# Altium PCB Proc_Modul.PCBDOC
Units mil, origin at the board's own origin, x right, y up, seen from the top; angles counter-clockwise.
Board outline 5390 x 3140 mil, 2 copper layers (Top Layer, Bottom Layer); 23 components, 59 nets, 260 pads, 83 vias.
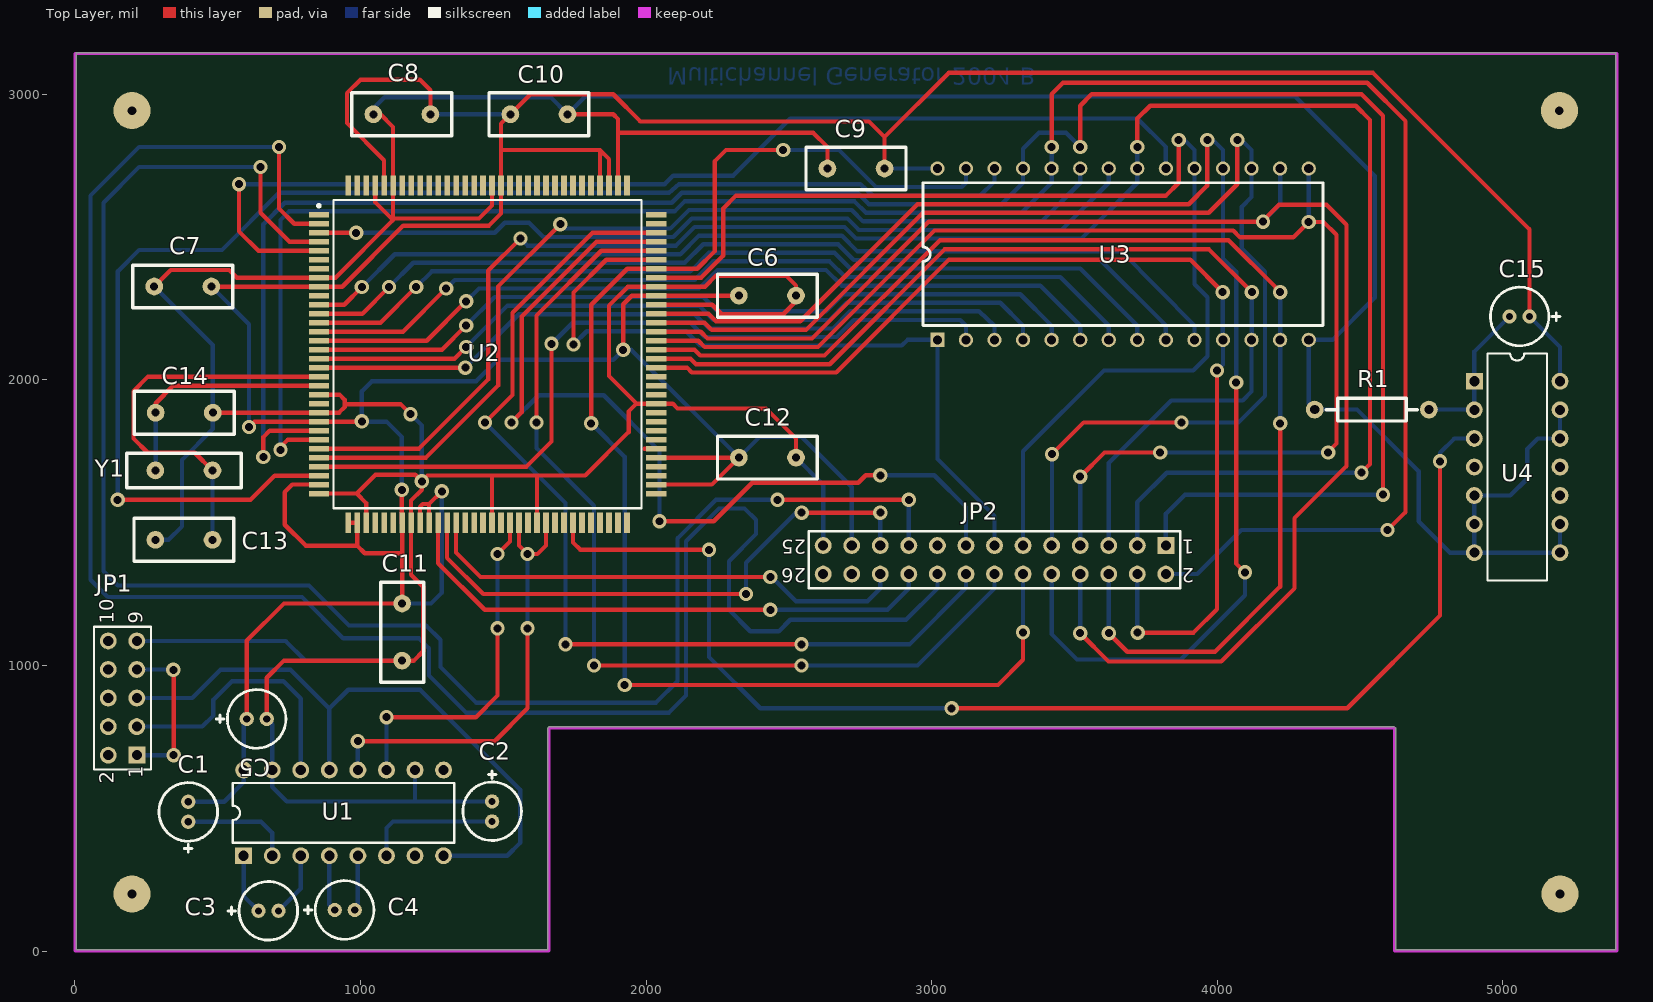
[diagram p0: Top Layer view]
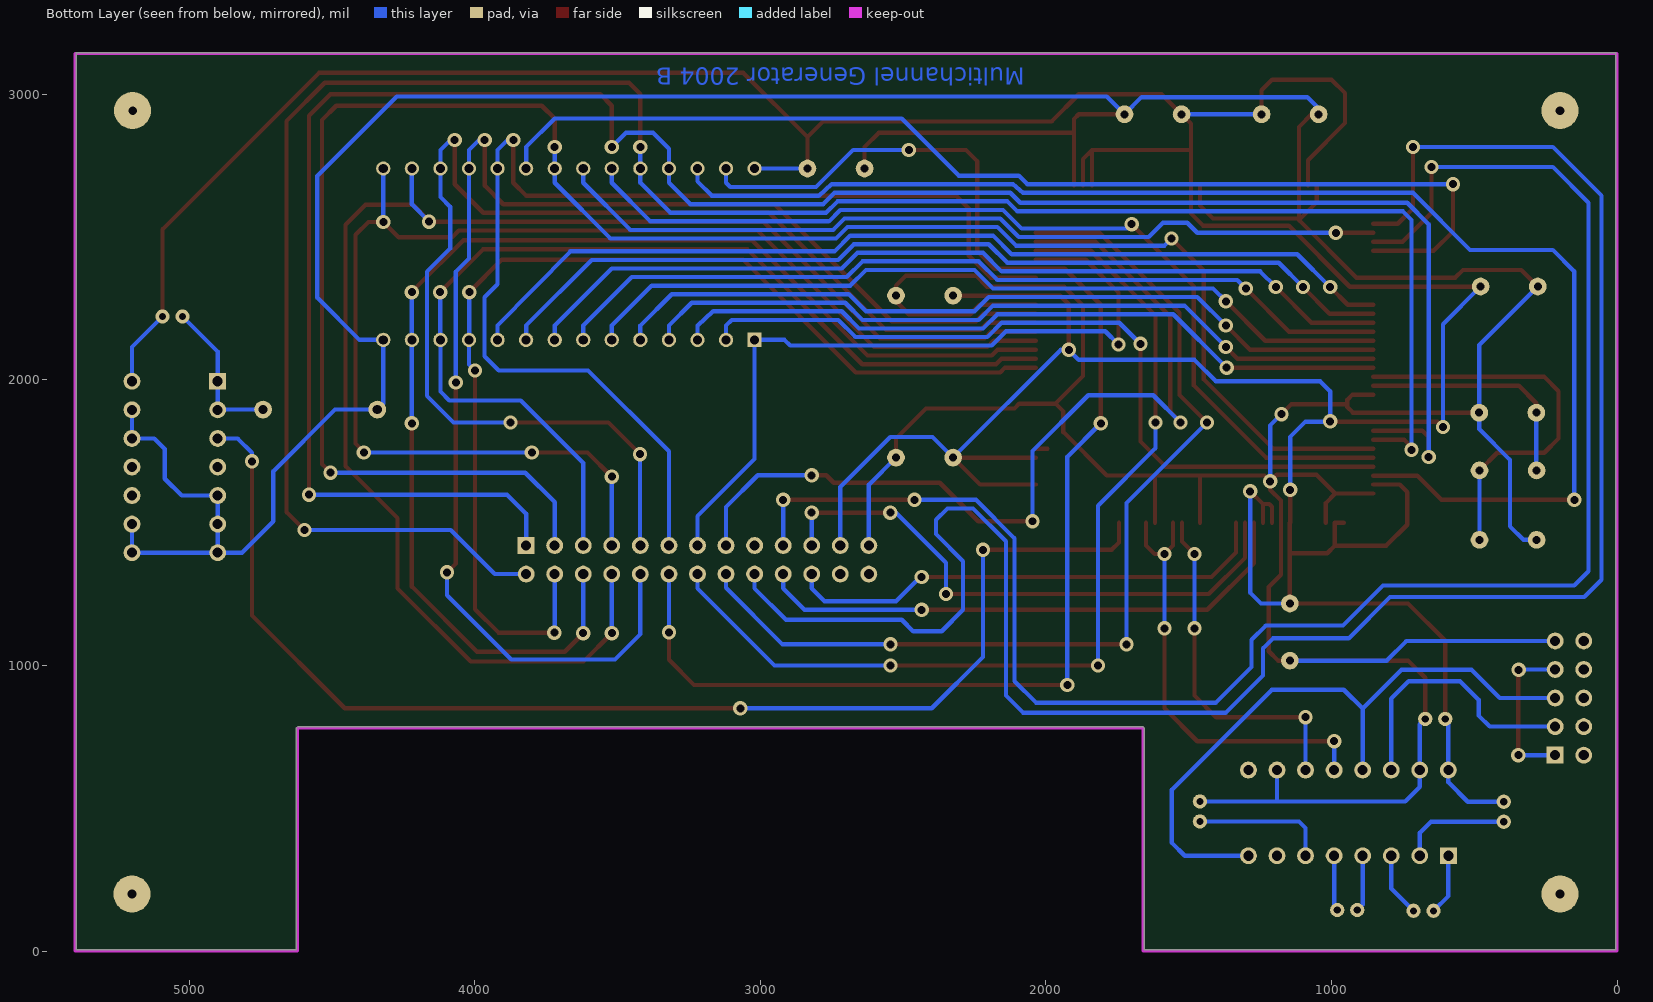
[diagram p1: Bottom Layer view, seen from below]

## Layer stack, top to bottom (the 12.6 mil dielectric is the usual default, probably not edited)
Top Layer: signal copper 1.4
Dielectric: dielectric 12.6, FR-4, Dk 4.8
Bottom Layer: signal copper 1.4

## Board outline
5,5 1655,5 1655,780 1660,785 4620,785 4625,780 4625,5 5395,5 5395,3145 5,3145

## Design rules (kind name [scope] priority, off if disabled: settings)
Clearance [All] p1: gap=10
ComponentClearance [All] p1: gap=10 collisioncheckmode=0
PolygonConnect [All] p1: connectstyle=Relief reliefconductorwidth=10 reliefentries=4 polygonreliefangle="90 Angle"
RoutingLayers [All] p1: top layer=Vertical bottom layer=Horizontal
RoutingVias [All] p1: holewidth=28 width=50 viastyle="Through Hole" minholewidth=28 minwidth=50 maxholewidth=28 maxwidth=50
SolderMaskExpansion [All] p1: expansion=4
TestPointUsage [All] p1: valid=0 allowmultiple=FALSE
Testpoint [All] p1: side=15 testpointundercomponent=TRUE minsize=40 maxsize=100 preferedsize=60 minholesize=0 maxholesize=40 preferedholesize=32 testpointgrid=1 style=1023 order=1234567890
Width 15mil [All] p1: maxlimit=20 minlimit=10 preferedwidth=10 toplayer_minwidth=15 toplayer_prefwidth=15 bottomlayer_minwidth=15 bottomlayer_prefwidth=15 minimp=50.000000 maximp=50.000000 favimp=50.000000
16 further rules are at their usual default settings.

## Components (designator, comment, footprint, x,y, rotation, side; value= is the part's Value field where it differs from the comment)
C1 "1uF" RB.07/.2 397,453 r90 top
C2 "1uF" RB.07/.2 1461,524 r270 top
C3 "1uF" RB.07/.2 643,141 r0 top
C4 "1uF" RB.07/.2 910,144 r0 top
C5 "4u7" RB.07/.2 602,813 r0 top
C6 "" RAD-0.2 2525,2295 r180 top
C7 "" RAD-0.2 278,2327 r0 top
C8 "" RAD-0.2 1045,2930 r0 top
C9 "" RAD-0.2 2635,2740 r0 top
C10 "100nF" RAD-0.2 1725,2930 r180 top
C11 "100nF" RAD-0.2 1146,1017 r90 top
C12 "100nF" RAD-0.2 2525,1728 r180 top
C13 "" RAD-0.2 482,1440 r180 top
C14 "" RAD-0.2 283,1885 r0 top
C15 "Cap Pol1" RB.07/.2 5093,2222 r180 top
JP1 "Header 5X2" HDR2X5 217,686 r90 top
JP2 "Header 13X2" HDR2X13 3820,1420 r180 top
R1 "Res2" AXIAL-0.4 4341,1896 r0 top
U1 "MAX232ACPE" DIP-16/X1.5 941,484 r0 top
U2 "ADSP-2181KS-160" QFP28x28-G128/Y1.8N 1445,2090 r0 top
U3 "27512" DIP28 3020,2140 r90 top
U4 "4093" DIP-14 5050,1695 r270 top
Y1 "XTAL" XTAL1 282,1683 r0 top

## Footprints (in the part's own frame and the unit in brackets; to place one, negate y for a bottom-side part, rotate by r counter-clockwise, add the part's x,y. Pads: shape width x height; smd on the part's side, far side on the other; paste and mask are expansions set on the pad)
AXIAL-0.4 [mil]
  round 62 hole 32: 1(0,0) 2(400,0)
  silkscreen extent 40,-40 360,40
DIP28 [mil]
  rect 50x50 hole 32: 1(0,0)
  round 50 hole 32: 2(0,-100) 3(0,-200) 4(0,-300) 5(0,-400) 6(0,-500) 7(0,-600) 8(0,-700) 9(0,-800) 10(0,-900) 11(0,-1000) 12(0,-1100) 13(0,-1200) 14(0,-1300) 15(600,-1300) 16(600,-1200) 17(600,-1100) 18(600,-1000) 19(600,-900) 20(600,-800) 21(600,-700) 22(600,-600) 23(600,-500) 24(600,-400) 25(600,-300) 26(600,-200) 27(600,-100) 28(600,0)
  silkscreen extent 50,-1350 550,50
DIP-14 [mm]
  rect 1.5x1.5 hole 0.9: 1(-7.62,-3.81)
  round 1.5 hole 0.9: 2(-5.08,-3.81) 3(-2.54,-3.81) 4(0,-3.81) 5(2.54,-3.81) 6(5.08,-3.81) 7(7.62,-3.81) 8(7.62,3.81) 9(5.08,3.81) 10(2.54,3.81) 11(0,3.81) 12(-2.54,3.81) 13(-5.08,3.81) 14(-7.62,3.81)
  silkscreen extent -10.1,-2.65 10.1,2.65
DIP-16/X1.5 [mm]
  rect 1.5x1.5 hole 0.9: 1(-8.89,-3.81)
  round 1.5 hole 0.9: 2(-6.35,-3.81) 3(-3.81,-3.81) 4(-1.27,-3.81) 5(1.27,-3.81) 6(3.81,-3.81) 7(6.35,-3.81) 8(8.89,-3.81) 9(8.89,3.81) 10(6.35,3.81) 11(3.81,3.81) 12(1.27,3.81) 13(-1.27,3.81) 14(-3.81,3.81) 15(-6.35,3.81) 16(-8.89,3.81)
  silkscreen extent -9.85,-2.65 9.85,2.65
HDR2X5 [mm]
  rect 1.5x1.5 hole 0.9: 1(0,0)
  round 1.5 hole 0.9: 2(0,2.54) 3(2.54,0) 4(2.54,2.54) 5(5.08,0) 6(5.08,2.54) 7(7.62,0) 8(7.62,2.54) 9(10.16,0) 10(10.16,2.54)
  silkscreen extent -1.27,-1.27 11.43,3.81
HDR2X13 [mm]
  rect 1.5x1.5 hole 0.9: 1(0,0)
  round 1.5 hole 0.9: 2(0,2.54) 3(2.54,0) 4(2.54,2.54) 5(5.08,0) 6(5.08,2.54) 7(7.62,0) 8(7.62,2.54) 9(10.16,0) 10(10.16,2.54) 11(12.7,0) 12(12.7,2.54) 13(15.24,0) 14(15.24,2.54) 15(17.78,0) 16(17.78,2.54) 17(20.32,0) 18(20.32,2.54) 19(22.86,0) 20(22.86,2.54) 21(25.4,0) 22(25.4,2.54) 23(27.94,0) 24(27.94,2.54) 25(30.48,0) 26(30.48,2.54)
  silkscreen extent -1.27,-1.27 31.75,3.81
QFP28x28-G128/Y1.8N [mm]
  rect 1.8x0.5 smd: 1(-15,12.4) 2(-15,11.6) 3(-15,10.8) 4(-15,10) 5(-15,9.2) 6(-15,8.4) 7(-15,7.6) 8(-15,6.8) 9(-15,6) 10(-15,5.2) 11(-15,4.4) 12(-15,3.6) 13(-15,2.8) 14(-15,2) 15(-15,1.2) 16(-15,0.4) 17(-15,-0.4) 18(-15,-1.2) 19(-15,-2) 20(-15,-2.8) 21(-15,-3.6) 22(-15,-4.4) 23(-15,-5.2) 24(-15,-6) 25(-15,-6.8) 26(-15,-7.6) 27(-15,-8.4) 28(-15,-9.2) 29(-15,-10) 30(-15,-10.8) 31(-15,-11.6) 32(-15,-12.4) 65(15,-12.4) 66(15,-11.6) 67(15,-10.8) 68(15,-10) 69(15,-9.2) 70(15,-8.4) 71(15,-7.6) 72(15,-6.8) 73(15,-6) 74(15,-5.2) 75(15,-4.4) 76(15,-3.6) 77(15,-2.8) 78(15,-2) 79(15,-1.2) 80(15,-0.4) 81(15,0.4) 82(15,1.2) 83(15,2) 84(15,2.8) 85(15,3.6) 86(15,4.4) 87(15,5.2) 88(15,6) 89(15,6.8) 90(15,7.6) 91(15,8.4) 92(15,9.2) 93(15,10) 94(15,10.8) 95(15,11.6) 96(15,12.4)
  rect 0.5x1.8 smd: 33(-12.4,-15) 34(-11.6,-15) 35(-10.8,-15) 36(-10,-15) 37(-9.2,-15) 38(-8.4,-15) 39(-7.6,-15) 40(-6.8,-15) 41(-6,-15) 42(-5.2,-15) 43(-4.4,-15) 44(-3.6,-15) 45(-2.8,-15) 46(-2,-15) 47(-1.2,-15) 48(-0.4,-15) 49(0.4,-15) 50(1.2,-15) 51(2,-15) 52(2.8,-15) 53(3.6,-15) 54(4.4,-15) 55(5.2,-15) 56(6,-15) 57(6.8,-15) 58(7.6,-15) 59(8.4,-15) 60(9.2,-15) 61(10,-15) 62(10.8,-15) 63(11.6,-15) 64(12.4,-15) 97(12.4,15) 98(11.6,15) 99(10.8,15) 100(10,15) 101(9.2,15) 102(8.4,15) 103(7.6,15) 104(6.8,15) 105(6,15) 106(5.2,15) 107(4.4,15) 108(3.6,15) 109(2.8,15) 110(2,15) 111(1.2,15) 112(0.4,15) 113(-0.4,15) 114(-1.2,15) 115(-2,15) 116(-2.8,15) 117(-3.6,15) 118(-4.4,15) 119(-5.2,15) 120(-6,15) 121(-6.8,15) 122(-7.6,15) 123(-8.4,15) 124(-9.2,15) 125(-10,15) 126(-10.8,15) 127(-11.6,15) 128(-12.4,15)
  silkscreen extent -15.12,-13.7 13.7,13.7
RAD-0.2 [mil]
  round 62 hole 28: 1(0,0) 2(200,0)
  silkscreen extent -75,-75 275,75
RB.07/.2 [mil]
  round 50 hole 25: 1(0,0) 2(70,0)
  silkscreen extent -107,-103 137,102
XTAL1 [mil]
  round 62 hole 28: 1(0,0) 2(200,0)
  silkscreen extent -100,-60 300,60

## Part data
C1 C2 C3 C4 C5: library part ELECTRO1
C6 C7 C8 C9 C10 C11 C12 C13 C14: library part Cap, "Capacitor"
C15: "Polarized Capacitor (Radial)"
JP1: "Header, 5-Pin, Dual row"
JP2: "Header, 13-Pin, Dual row"
R1: "Resistor"
U1: "+5V Powered, Multi-Channel RS-232 Driver/Receiver"
U2: "40 MIPS, 5V, 2 Serial Ports, Host Port, 80 KB RAM"
Y1: "Crystal Oscillator"

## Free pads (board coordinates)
  round 130 hole 30: 0(200,200) 0(200,2943) 0(5198,2943) 0(5200,200)

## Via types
v1: diameter 50, hole 28, Top Layer to Bottom Layer, 83 vias

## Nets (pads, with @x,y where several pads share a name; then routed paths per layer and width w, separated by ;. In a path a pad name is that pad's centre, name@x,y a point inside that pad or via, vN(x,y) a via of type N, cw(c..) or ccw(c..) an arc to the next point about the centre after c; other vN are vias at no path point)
/BMS: U2.5 U3.20 | length 3929.2
  Top Layer w15: v1(575,2685) 575,2520 642.8,2452.2 U2.5
  Bottom Layer w15: v1(575,2685) 2065,2685 2095,2715 2305,2715 2505,2915 3720,2915 3820,2815 U3.20
/IOS: JP2.19 U2.4 | length 6111.4
  Top Layer w15: v1(650,2745) 650,2585 751.3,2483.7 U2.4 ; v1(2460,1580) v1(2920,1580)
  Bottom Layer w15: v1(650,2745) 225,2745 100,2620 100,1330 150,1280 820,1280 960,1140 1230,1140 1280,1090 1280,995 1405,870 2035,870 2110,945 2110,1445 2245,1580 v1(2460,1580) ; JP2.19 v1(2920,1580)
/RD: U2.3 U3.22 | length 2962.7
  Top Layer w15: U2.3 984.8,2515.2 v1(985,2515)
  Bottom Layer w15: v1(985,2515) 1470,2515 1505,2550 1590,2550 1640,2500 2095,2500 2160,2565 2705,2565 2745,2525 3455,2525 3620,2690 U3.22
/WR: JP2.18 U2.2 | length 6886.8
  Top Layer w15: v1(715,2815) 715,2600 768.31,2546.69 U2.2
  Bottom Layer w15: v1(715,2815) 225,2815 55,2645 55,1300 115,1240 795,1240 940,1095 1205,1095 1240,1060 1240,965 1370,835 2080,835 2140,895 2140,1435 2255,1550 2345,1550 2385,1510 2385,1460 2290,1365 2290,1195 2365,1120 2465,1120 2505,1160 2910,1160 3020,1270 JP2.18
A0: U2.11 U3.10 | length 3347.7
  Top Layer w15: U2.11 943.23,2263.23 v1(1005,2325)
  Bottom Layer w15: v1(1005,2325) 1120,2440 2120,2440 2185,2505 2685,2505 2740,2450 3665,2450 3920,2190 U3.10
A1: U2.12 U3.9 | length 3234.4
  Top Layer w15: U2.12 1006.73,2231.73 v1(1100,2325)
  Bottom Layer w15: v1(1100,2325) 1185,2410 2135,2410 2200,2475 2672.43,2475 2727.43,2420 3590,2420 3820,2190 U3.9
A2: U2.13 U3.8 | length 3122.6
  Top Layer w15: U2.13 1070.24,2200.24 v1(1195,2325)
  Bottom Layer w15: v1(1195,2325) 1250,2380 2155,2380 2220,2445 2660,2445 2715,2390 3520,2390 3720,2190 U3.8
A3: U2.14 U3.7 | length 3010.8
  Top Layer w15: U2.14 1148.74,2168.74 v1(1300,2320)
  Bottom Layer w15: v1(1300,2320) 1330,2350 2170,2350 2235,2415 2642.43,2415 2697.43,2360 3450,2360 3620,2190 U3.7
A4: U2.15 U3.6 | length 2898.9
  Top Layer w15: U2.15 1232.24,2137.24 v1(1370,2275)
  Bottom Layer w15: v1(1370,2275) 1415,2320 2185,2320 2250,2385 2630,2385 2685,2330 3380,2330 3520,2190 U3.6
A5: U2.16 U3.5 | length 2783
  Top Layer w15: U2.16 1285.75,2105.75 v1(1370,2190)
  Bottom Layer w15: v1(1370,2190) 1470,2290 2200,2290 2250,2240 2630,2240 2690,2300 3310,2300 3420,2190 U3.5
A6: U2.17 U3.4 | length 2671.2
  Top Layer w15: U2.17 1329.25,2074.25 v1(1370,2115)
  Bottom Layer w15: v1(1370,2115) 1515,2260 2185,2260 2235,2210 2642.43,2210 2702.43,2270 3240,2270 3320,2190 U3.4
A7: U2.18 U3.3 | length 2558
  Top Layer w15: U2.18 v1(1367.24,2042.76)
  Bottom Layer w15: v1(1367.24,2042.76) 1554.49,2230 2170,2230 2220,2180 2654.85,2180 2714.85,2240 3165,2240 3220,2190 U3.3
A8: JP2.1 U2.25 U3.25 | length 7683.2
  Top Layer w15: v1(660,1730) 660,1800 682.28,1822.28 U2.25 ; v1(3520,2815) 3520,2960 3560,3000 4505,3000 4580,2925 v1(4580,1598)
  Bottom Layer w15: v1(660,1730) 660,2545 735,2620 2090,2620 2125,2655 2740,2655 2780,2615 3245,2615 3320,2690 3320,2809 3376,2865 3470,2865 v1(3520,2815) ; JP2.1 3820,1531 3887,1598 v1(4580,1598)
A9: JP2.2 U2.26 U3.24 | length 7667.2
  Top Layer w15: v1(720,1755) 720,1765 745.79,1790.79 U2.26 U2.26@853.66,1790 ; v1(3420,2815) 3420,3000 3460,3040 4525,3040 4659,2906 4659,1537 v1(4596,1474)
  Bottom Layer w15: v1(720,1755) 720,2560 750,2590 2100,2590 2135,2625 2730,2625 2770,2585 3315,2585 3420,2690 U3.24 v1(3420,2815) ; JP2.2 3930,1320 4084,1474 v1(4596,1474)
A10: JP2.3 U2.27 U3.21 | length 6834.5
  Top Layer w15: U2.27 1205.29,1759.29 1447,2001 1447,2382 v1(1560,2495) ; v1(3720,2815) 3720,2915 3765,2960 4485,2960 4535,2910 4535,1705 v1(4505,1675)
  Bottom Layer w15: v1(1560,2495) 1585,2470 2105,2470 2170,2535 2695,2535 2735,2495 3525,2495 3720,2690 U3.21 v1(3720,2815) ; JP2.3 3720,1572 3823,1675 v1(4505,1675)
A11: U2.28 U3.23 | length 3362.9
  Top Layer w15: U2.28 1229.8,1727.8 1482,1980 1482,2327 v1(1700,2545)
  Bottom Layer w15: v1(1700,2545) 1715,2530 2085,2530 2150,2595 2720,2595 2760,2555 3385,2555 3520,2690 U3.23
A12: U2.29 U3.2 | length 2786.6
  Top Layer w15: U2.29 1581.3,1696.3 1669,1784 v1(1669,2126)
  Bottom Layer w15: v1@1666,2119 1666,2123 1743,2200 2155,2200 2205,2150 2667.28,2150 2727.28,2210 3100,2210 3120,2190 U3.2
A13: U2.30 U3.26 | length 4815.5
  Top Layer w15: v1(150,1580) 615,1580 699.8,1664.8 U2.30
  Bottom Layer w15: v1(150,1580) 150,2380 225,2455 515,2455 715,2655 2080,2655 2115,2685 2750,2685 2795,2645 3170,2645 3220,2695 U3.26
D8: JP2.4 U2.79 U3.11 | length 3837.7
  Top Layer w15: U2.79 2143.24,2042.76 2160,2026 2666,2026 3061,2421 3905,2421 v1(4019,2307) ; v1(3721,1115) 3917,1115 3999,1197 v1(3999,2033)
  Bottom Layer w15: v1@3720,1116 JP2.4 ; v1(3999,2033) 4020,2054 U3.11 ; v1(4019,2307) U3.11@4019,2141 ; U3.11@4019,2141 U3.11 ; U3.11@4019,2141 U3.11
D9: JP2.5 U2.80 U3.12 | length 3563
  Top Layer w15: U2.80 2155.75,2074.25 2175,2055 2643,2055 3045,2457 3971,2457 v1(4121,2307)
  Bottom Layer w15: JP2.5 3620,1709 3839,1928 4089,1928 4120,1959 U3.12 4121,2141 v1(4121,2307)
D10: JP2.6 U2.81 U3.13 | length 4395.7
  Top Layer w15: U2.81 2169.25,2105.75 2190,2085 2625,2085 3029,2489 4039,2489 4205,2323 4205,2322 v1(4220,2307) ; v1(3620,1113) 3685,1048 3992,1048 4220,1276 v1(4220,1848)
  Bottom Layer w15: v1(3620,1113) JP2.6 ; v1(4220,1848) v1(4220,2307)
D11: JP2.7 U2.82 U3.15 | length 4715.8
  Top Layer w15: U2.82 2182.76,2137.24 2205,2115 2602,2115 3010,2523 4056,2523 4080,2499 4266,2499 v1(4320,2553) 4372,2553 4417,2508 4417,1777 4388,1748 v1(4388,1746) ; v1(3520,1661) 3605,1746 v1(3800,1746)
  Bottom Layer w15: JP2.7 v1(3520,1661) ; v1(3800,1746) v1(4388,1746) ; v1(4320,2553) U3.15
D12: JP2.8 U2.83 U3.16 | length 5314.2
  Top Layer w15: U2.83 2191.26,2168.74 2215,2145 2581,2145 2990,2554 v1(4160,2554) 4160,2557 4216,2613 4382,2613 4452,2543 4452,1698 4270,1516 4270,1270 4014,1014 3619,1014 v1(3520,1113)
  Bottom Layer w15: v1(3520,1113) JP2.8 ; v1(4160,2554) 4160,2555 4220,2615 U3.16
D13: JP2.9 U2.84 U3.17 | length 4520.2
  Top Layer w15: U2.84 2204.76,2200.24 2230,2175 2560,2175 2970,2585 3970,2585 4070,2685 v1(4070,2840) ; v1(3421,1740) 3532,1851 v1(3875,1851)
  Bottom Layer w15: JP2.9 3421,1421 v1(3421,1740) ; v1(3875,1851) 4074,1851 4167,1944 4167,2379 4086,2460 4086,2606 4120,2640 4120,2805 v1@4085,2840
D14: JP2.10 U2.85 U3.18 | length 4974.7
  Top Layer w15: U2.85 2218.27,2231.73 2245,2205 2540,2205 2950,2615 3900,2615 3965,2680 v1(3965,2840) ; v1(4066,1991) 4066,1357 v1(4097,1326)
  Bottom Layer w15: JP2.10 3420,1110 3509,1021 3872,1021 4097,1246 v1(4097,1326) ; v1(3965,2840) 3985,2840 4020,2805 4020,2425 4066,2379 v1(4066,1991)
D15: JP2.11 U2.89 U3.19 | length 4138.2
  Top Layer w15: U2.89 2192.72,2357.72 2270,2435 2270,2600 2315,2645 3820,2645 3865,2690 v1(3865,2840)
  Bottom Layer w15: JP2.11 3320,1750 3603,2033 3916,2033 3966,2083 3966,2289 3920,2335 3920,2805 3885,2840 v1(3865,2840)
D16: JP2.12 U2.90 U3.27 | length 4942
  Top Layer w15: v1(1808,1848) 1808,2263 1934.21,2389.21 2179.21,2389.21 2240,2450 2240,2765 2280,2805 v1(2480,2805) ; v1(1925,932) 3232,932 3320,1020 v1(3320,1116)
  Bottom Layer w15: v1(1808,1848) 1925,1731 v1(1925,932) ; v1(2480,2805) 2675,2805 2805,2675 3105,2675 3120,2690 U3.27 ; v1(3320,1116) JP2.12
D17: JP2.13 U2.91 U3.1 | length 2644
  Top Layer w15: v1(1746,2124) 1746,2306 1860.71,2420.71 U2.91
  Bottom Layer w15: v1(1746,2124) 1792,2170 2140,2170 2190,2120 2895,2120 2915,2140 U3.1 3020,1723 3220,1523 JP2.13
D18: JP2.14 U2.92 | length 3386.2
  Top Layer w15: v1(1616,1851) 1616,2225 1843.2,2452.2 U2.92 ; v1(1818,1000) v1(2544,1000)
  Bottom Layer w15: v1(1616,1851) 1616,1761 1818,1559 v1(1818,1000) ; v1(2544,1000) 2950,1000 3220,1270 JP2.14
D19: JP2.15 U2.93 | length 3169.7
  Top Layer w15: v1(1529,1851) 1565,1887 1565,2222 1826.7,2483.7 U2.93 ; v1(2047,1505) 2237,1505 2372,1640 2743,1640 2769,1666 v1(2820,1666)
  Bottom Layer w15: v1(1529,1851) 1624,1946 1852,1946 2047,1751 v1(2047,1505) ; v1(2820,1666) 3009,1666 3120,1555 JP2.15
D20: JP2.16 U2.94 | length 3472
  Top Layer w15: v1(1436,1851) 1532,1947 1532,2235 1812.2,2515.2 U2.94 ; v1@1716,1072 v1(1718,1074) v1(2544,1074)
  Bottom Layer w15: v1(1436,1851) 1718,1569 v1(1718,1074) ; v1(2544,1074) 2922,1074 3120,1272 JP2.16
FL0: JP2.20 U2.43 | length 1938.1
  Top Layer w15: U2.43 1271.77,1358.23 1435,1195 v1(2435,1195)
  Bottom Layer w15: v1(2435,1195) 2845,1195 2920,1270 JP2.20
FL1: JP2.21 U2.44 | length 1989.4
  Top Layer w15: U2.44 1303.27,1376.73 1430,1250 v1(2350,1250) ; v1(2545,1535) v1(2820,1535)
  Bottom Layer w15: v1(2350,1250) 2350,1360 2525,1535 v1(2545,1535) ; JP2.21 v1(2820,1535)
FL2: JP2.22 U2.45 | length 1728.6
  Top Layer w15: U2.45 1334.76,1395.24 1420,1310 v1(2435,1310)
  Bottom Layer w15: v1(2435,1310) 2440,1310 2525,1225 2775,1225 2820,1270 JP2.22
GND: C2.1 C5.2 C6.1 C7.1 C8.1 C9.1 C10.1 C11.1 C12.1 C13.2 C14.2 JP1.9 JP2.25 R1.1 U1.10 U1.15 U2.8 U2.21 U2.23 U2.32 U2.35 U2.40 U2.49 U2.54 U2.75 U2.86 U2.88 U2.98 U2.112 U2.123 U2.125 U3.14 U4.5 U4.6 U4.7 U4.8 U4.9 U4.12 U4.13 | length 19969.4
  Top Layer w15: C7.1 336,2385 540,2385 567.28,2357.72 U2.8 912.72,2357.72 1114.29,2559.29 ; C14.2 854.17,1885 U2.23 925.28,1885.28 945,1905 945,1930 926.73,1948.27 U2.21 ; C5.2 672,957 732,1017 C11.1 1187,1017 1220,1050 1220,1275 1177.28,1317.72 U2.40 1177.28,1577.28 1215,1615 v1(1215,1645) ; U2.32 986.81,1601.81 ; 945,1915 1140,1915 v1(1175,1880) ; U2.35 1019.8,1568.82 986.81,1601.81 ; C8.1 1070,2930 1114.29,2885.71 U2.123 1114.29,2559.29 ; U2.125 1051.3,2622.28 1114.29,2559.29 ; 1120,2565 1415,2565 1460.75,2610.75 U2.112 ; U2.49 1460.75,1664.25 1461,1664.5 ; 1618,1665 1618.23,1664.77 U2.54 ; C10.1 1885,2930 1901.69,2913.31 1901.69,2870 ; U2.98 1901.69,2870 ; U2.86 2231.77,2263.23 2265,2230 2480,2230 2525,2275 C6.1 2525,2330 2490,2365 2245,2365 2206.22,2326.22 U2.88 1936.22,2326.22 1870,2260 1870,2013.54 1966.77,1916.77 ; C12.1 2525,1795 2420,1900 2110,1900 2093.23,1916.77 1966.77,1916.77 ; C9.1 2635,2815 2585,2865 1906.69,2865 1901.69,2870 ; 986.81,1601.81 1053,1668 1192,1668 v1(1215,1645) ; v1(1215,1645) 1235,1665 1787,1665 1939,1817 1939,1889 1966.77,1916.77
  Bottom Layer w15: JP1.9 738,1086 807,1017 C11.1 ; C7.1 483,2122 C14.2 483,1828 375,1720 375,1487 328,1440 C13.2 ; C5.2 691,794 691,575 742,524 C2.1 C2.1@1460,523 ; C8.1 1045,2950 1085,2990 1665,2990 C10.1 1787,2992 4273,2992 4551,2714 4551,2288 4403,2140 U3.14 4320,1917 R1.1 4489,1896 4705,1680 4705,1505 4815,1395 U4.8 U4.9 ; v1(1175,1880) 1215,1840 v1(1215,1645) ; 1190,524 1191,525 U1.10 ; C12.1 2620,1633 JP2.25 ; U4.7 U4.6 U4.5 5026,1595 5085,1654 5085,1758 5122,1795 U4.12 U4.13
NetC1_1: C1.1 U1.2 | length 390.2
  Bottom Layer w15: C1.1 652,453 691,414 U1.2
NetC2_2: C2.2 U1.6 | length 476.5
  Bottom Layer w15: U1.6 1091,431 1114,454 C2.2
NetC3_1: C3.1 U1.1 | length 214.5
  Bottom Layer w15: U1.1 591,193 C3.1
NetC3_2: C3.2 U1.3 | length 225.3
  Bottom Layer w15: C3.2 791,219 U1.3
NetC4_1: C4.1 U1.4 | length 197.9
  Bottom Layer w15: U1.4 891,163 C4.1
NetC4_2: C4.2 U1.5 | length 194.6
  Bottom Layer w15: C4.2 991,155 U1.5
NetC13_1: C13.1 U2.19 Y1.2 | length 1402.1
  Top Layer w15: Y1.2 420,1745 255,1745 205,1795 205,1960 256.26,2011.26 U2.19
  Bottom Layer w15: C13.1 Y1.2
NetC14_1: C14.1 U2.20 Y1.1 | length 832.1
  Top Layer w15: C14.1 283,1918 344.76,1979.76 U2.20
  Bottom Layer w15: Y1.1@283,1682.98 C14.1
NetC15_2: C15.2 R1.2 U4.1 U4.2 | length 537.4
  Bottom Layer w15: R1.2 4899,1896 U4.2 U4.1 4900,2099 C15.2
NetJP1_1: JP1.1 JP1.7 | length 556.8
  Top Layer w15: v1(345,985) 346,984 v1(346,686)
  Bottom Layer w15: JP1.1 v1(346,686) ; JP1.7 344,986 v1(345,985)
NetJP1_3: JP1.3 U1.14 | length 947.3
  Bottom Layer w15: JP1.3 446,786 485,825 485,880 550,945 730,945 791,884 U1.14
NetJP1_5: JP1.5 U1.8 U1.13 | length 2299.3
  Bottom Layer w15: JP1.5 411,886 510,985 755,985 891,849 ; U1.13 891,849 ; U1.8 1514,334 1559,379 1559,565 1209,915 957,915 891,849
NetU1_11: U1.11 U2.51 | length 1228
  Top Layer w15: v1(1091,819) 1404,819 1480,895 v1(1480,1130) ; v1(1480,1390) 1523.74,1433.74 U2.51
  Bottom Layer w15: U1.11 v1(1091,819) ; v1(1480,1130) v1(1480,1390)
NetU1_12: U1.12 U2.52 U2.55 | length 1571.3
  Top Layer w15: v1(991,735) 1470,735 1585,850 v1(1585,1130) ; U2.52 1555.24,1419.76 v1(1585,1390) 1619.45,1390 1649.72,1420.28 U2.55
  Bottom Layer w15: v1@990,745 991,744 v1(991,735) U1.12 ; v1(1585,1130) v1(1585,1390)
NetU2_58: U2.58 U4.3 | length 4410
  Top Layer w15: U2.58 1744.21,1430.79 1770,1405 v1(2220,1405) ; v1(3070,850) 4455,850 4780,1175 v1(4780,1715)
  Bottom Layer w15: v1(2220,1405) 2220,1030 2400,850 v1(3070,850) ; v1(4780,1715) 4780,1745 4830,1795 U4.3
NetU2_70: U2.70 | length 41.3
  Top Layer w15: 1994.29,1759.29 U2.70
NetU2_71: U2.71
NetU2_72: U2.72
NetU2_73: U2.73
NetU2_74: U2.74
NetU2_76: U2.76
NetU2_77: U2.77
NetU2_78: U2.78
VDD: C1.2 C5.1 C6.2 C7.2 C8.2 C9.2 C10.2 C11.2 C12.2 C15.1 JP2.23 U1.16 U2.9 U2.24 U2.31 U2.33 U2.34 U2.39 U2.41 U2.42 U2.66 U2.69 U2.87 U2.99 U2.100 U2.111 U2.124 U3.28 U4.14 | length 16082.1
  Top Layer w15: C7.2 478.78,2326.22 U2.9 936.22,2326.22 1150,2540 1450,2540 1492.24,2582.24 U2.111 1492.24,2897.24 C10.2 1595,3000 1885,3000 1980,2905 2780,2905 2835,2850 ; C5.1 602,1087 732,1217 C11.2 1146,1499.24 U2.39 ; v1(610,1835) 628.78,1853.78 U2.24 v1@1003.78,1853.78 ; U2.31 761.31,1633.31 735,1607 735,1493 808.31,1419.69 988.31,1419.69 ; U2.33 U2.34 988.31,1419.69 ; U2.124 1082.8,2769.2 953,2899 953,3004 1000,3051 1208,3051 1245,3014 C8.2 ; U2.39@1145,1500.24 v1(1145,1615) ; 1146,1393 1015,1393 988.31,1419.69 ; U2.41 1208.78,1555.78 1218.28,1565.28 1240.28,1565.28 ; U2.42 1240.28,1565.28 ; v1(1285,1610) 1240.28,1565.28 ; 1492.24,2807 1494.54,2804.7 1838.7,2804.7 ; U2.100 1838.7,2804.7 ; U2.99 1870.2,2772.8 1839,2804 1839,2805 1838.7,2804.7 ; v1(1920,2105) 1920,2265 1949.72,2294.72 U2.87 ; U2.66 2230.31,1633.31 C12.2 ; U2.69 C12.2@2320.8,1727.8 ; U2.87@2035.83,2295 C6.2 ; C9.2 2835,2850 ; C15.1 5093,2527 4545,3075 3060,3075 2835,2850
  Bottom Layer w15: C1.2 523,523 591,591 C5.1@591,802 ; C7.2 610,2195 v1(610,1835) ; v1@1003.78,1853.78 1091.22,1853.78 1145,1800 v1(1145,1615) ; v1(1005,1855) 1005,1960 1040,1995 1405,1995 1480,2070 1885,2070 v1(1920,2105) 1948,2105 C12.2 2397,1800 2545,1800 2720,1625 JP2.23 ; C11.2 1247,1217 1285,1255 v1(1285,1610) ; C8.2 C10.2 ; C9.2 U3.28 ; C15.1 5200,2115 U4.14
pads on no net: JP1.2 JP1.4 JP1.6 JP1.8 JP1.10 JP2.17 JP2.24 JP2.26 U1.7 U1.9 U2.1 U2.6 U2.7 U2.10 U2.22 U2.36 U2.37 U2.38 U2.46 U2.47 U2.48 U2.50 U2.53 U2.56 U2.57 U2.59 U2.60 U2.61 U2.62 U2.63 U2.64 U2.65 U2.67 U2.68 U2.95 U2.96 U2.97 U2.101 U2.102 U2.103 U2.104 U2.105 U2.106 U2.107 U2.108 U2.109 U2.110 U2.113 U2.114 U2.115 U2.116 U2.117 U2.118 U2.119 U2.120 U2.121 U2.122 U2.126 U2.127 U2.128 U4.4 U4.10 U4.11

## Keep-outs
Keep-Out Layer:
  lines w10: 0,0 0,3143 5400,3143 5400,0 4620,0 4620,780 1660,780 1660,0 0,0

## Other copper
Bottom Layer:
  text "Multichannel Generator 2004 B" at 2074,3093 h60 r180

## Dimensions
0,0 to 1660,0 on Mechanical 1
1660,0 to 4620,0 on Mechanical 1
4620,0 to 5400,0 on Mechanical 1
5400,0 to 5400,3143 on Mechanical 1
200,266 to 200,134 on Mechanical 1
200,2943 to 0,3143 on Mechanical 1
200,2943 to 0,3143 on Mechanical 1
4620,0 to 4620,780 on Mechanical 1
0,0 to 5400,0 on Mechanical 1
